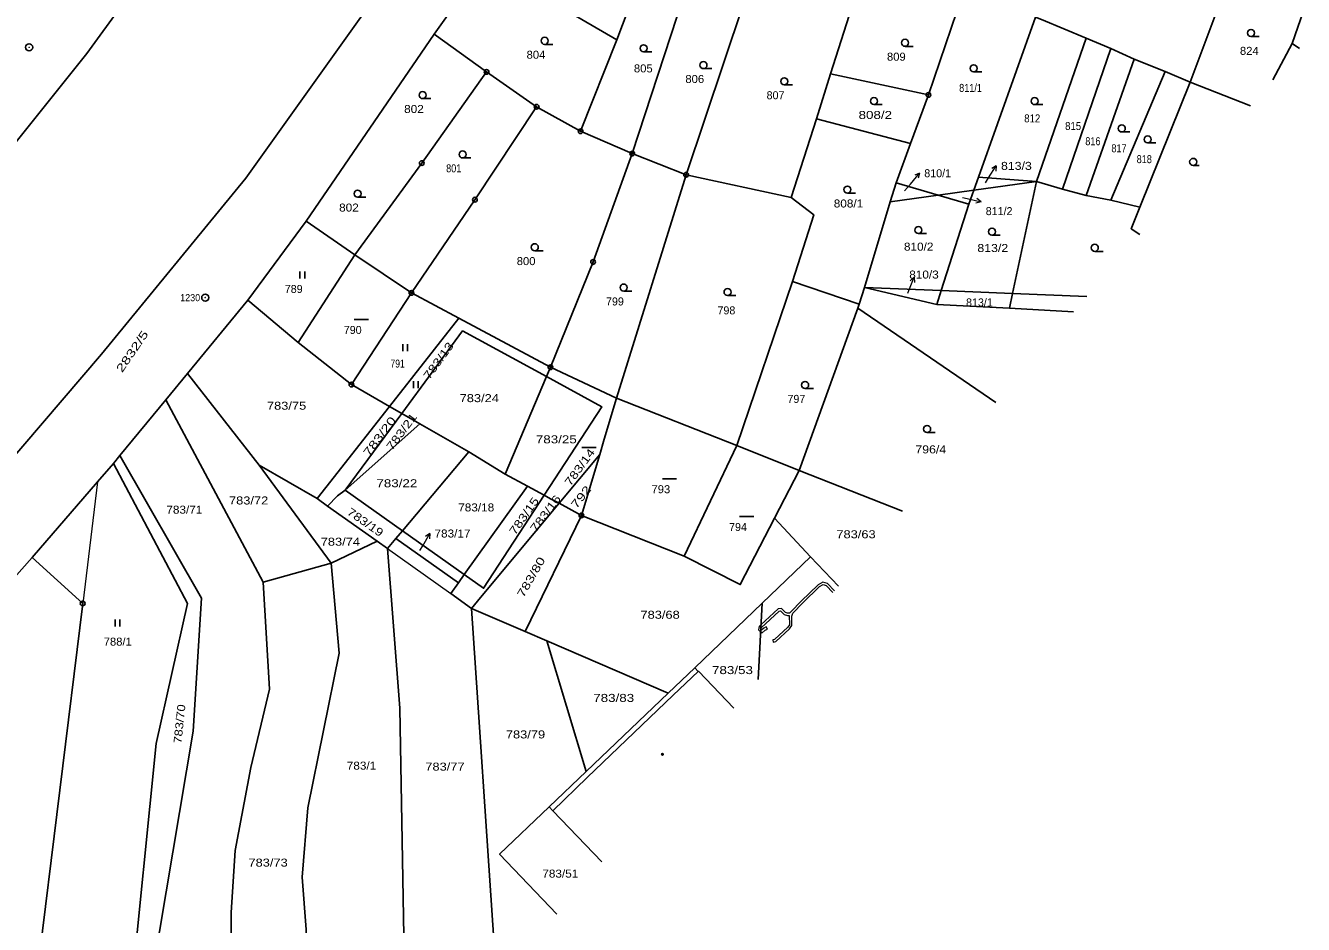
# Model space of a CAD drawing. Extents: x -546984 to -546090, y -1194931 to -1194069.
# Drawn here: x -546588.4 to -546317, y -1194754.2 to -1194563.2 of the extents above; entities that cross this region are included whole.
import ezdxf
from ezdxf.enums import TextEntityAlignment as Align

# ---------------------------------------------------------------- set-up
doc = ezdxf.new("R2010")
doc.units = 0
doc.header["$LTSCALE"] = 0.68
for name, color, linetype, lineweight in [('1', 7, 'Continuous', 25), ('13', 7, 'Continuous', 13), ('3', 7, 'Continuous', 25), ('4', 7, 'Continuous', 13), ('5', 7, 'Continuous', 25), ('7', 7, 'Continuous', 13), ('8', 7, 'Continuous', 25)]:
    doc.layers.add(name, color=color, linetype=linetype, lineweight=lineweight)
doc.layers.add('2', color=7, linetype='Continuous')

msp = doc.modelspace()

# ---------------------------------------------------------------- linework, layer by layer
at = {"layer": '1'}
for p, q in [((-546459.53, -1194590.43), (-546444.71, -1194545.11)), ((-546332.93, -1194553.62), (-546341, -1194575.24)), ((-546316.96, -1194560.09), (-546319.33, -1194567.05)), ((-546501.59, -1194565.05), (-546528.77, -1194604.78)), ((-546490.48, -1194573.07), (-546501.59, -1194565.05)), ((-546470.5, -1194585.68), (-546462.81, -1194566.22)), ((-546357.87, -1194568.11), (-546363.1, -1194565.9)), ((-546352.89, -1194570.35), (-546357.87, -1194568.11)), ((-546319.33, -1194567.05), (-546323.492, -1194574.76)), ((-546317.768, -1194568.087), (-546319.33, -1194567.05)), ((-546346.32, -1194572.96), (-546352.89, -1194570.35)), ((-546479.84, -1194580.46), (-546490.48, -1194573.07)), ((-546396.63, -1194577.94), (-546417.4, -1194573.5)), ((-546357.85, -1194600.33), (-546346.32, -1194572.96)), ((-546341, -1194575.24), (-546346.32, -1194572.96)), ((-546328.24, -1194580.295), (-546341, -1194575.24)), ((-546400.43, -1194588.27), (-546420.43, -1194583.03)), ((-546394.53, -1194599.25), (-546403.5, -1194596.62)), ((-546386.98, -1194598.21), (-546386.01, -1194595.44)), ((-546373.64, -1194596.38), (-546386.98, -1194598.21)), ((-546378.75, -1194620.15), (-546373.64, -1194596.38)), ((-546404.72, -1194600.65), (-546394.53, -1194599.25)), ((-546394.53, -1194599.25), (-546386.98, -1194598.21)), ((-546388.02, -1194601.16), (-546394.53, -1194599.25)), ((-546388.02, -1194601.16), (-546386.98, -1194598.21)), ((-546363.12, -1194599.31), (-546357.85, -1194600.33)), ((-546528.77, -1194604.78), (-546541.17, -1194621.53)), ((-546518.46, -1194611.94), (-546528.77, -1194604.78)), ((-546496.38, -1194625.39), (-546506.45, -1194620.01)), ((-546394.86, -1194622.45), (-546410.22, -1194618.84)), ((-546394.86, -1194622.45), (-546393.92, -1194619.52)), ((-546378.75, -1194620.15), (-546393.92, -1194619.52)), ((-546379.42, -1194623.27), (-546378.75, -1194620.15)), ((-546362.992, -1194620.804), (-546378.75, -1194620.15)), ((-546541.17, -1194621.53), (-546554, -1194637.12)), ((-546411.65, -1194623.24), (-546382.303, -1194643.315)), ((-546530.52, -1194630.57), (-546519.2, -1194639.51)), ((-546554, -1194637.12), (-546558.63, -1194642.75)), ((-546538.81, -1194656.63), (-546554, -1194637.12)), ((-546519.2, -1194639.51), (-546511.09, -1194644.15)), ((-546486.54, -1194658.5), (-546477.76, -1194637.81)), ((-546558.63, -1194642.75), (-546568.37, -1194654.58)), ((-546537.9, -1194681.47), (-546558.63, -1194642.75)), ((-546520.48, -1194661.94), (-546508.48, -1194645.64)), ((-546494.24, -1194653.78), (-546504.67, -1194647.82)), ((-546494.24, -1194653.78), (-546508.35, -1194670.55)), ((-546568.37, -1194654.58), (-546569.74, -1194656.25)), ((-546475.09, -1194664.7), (-546466.45, -1194654.33)), ((-546526.45, -1194663.73), (-546538.81, -1194656.63)), ((-546402.113, -1194666.407), (-546424.11, -1194657.73)), ((-546508.35, -1194670.55), (-546520.48, -1194661.94)), ((-546429.33, -1194667.88), (-546421.68, -1194676.11)), ((-546513.72, -1194672.79), (-546523.48, -1194677.44)), ((-546495.21, -1194679.88), (-546496.47, -1194681.64)), ((-546488.9, -1194757.45), (-546493.69, -1194687.04)), ((-546482.25, -1194691.97), (-546493.69, -1194687.04)), ((-546469.33, -1194721.69), (-546477.68, -1194693.94)), ((-546451.9, -1194705.05), (-546446.26, -1194699.66)), ((-546451.9, -1194705.05), (-546469.33, -1194721.69)), ((-546477.21, -1194729.22), (-546469.33, -1194721.69))]:
    msp.add_line(p, q, dxfattribs=at)
for points in [[(-546389.24, -1194211.62), (-546383.21, -1194213.85), (-546381.43, -1194214.52), (-546374.55, -1194220.96), (-546389.16, -1194255.29), (-546392.45, -1194260.52), (-546401.16, -1194281.84), (-546427.1, -1194334), (-546466.91, -1194406.62), (-546525.73, -1194500.91), (-546575.37, -1194569.17), (-546611.42, -1194614.13), (-546654.08, -1194661.28), (-546675.45, -1194680.69), (-546700.89, -1194697.8)], [(-546653.83, -1194720.11), (-546626.66, -1194696.55), (-546572.27, -1194633.02), (-546541.58, -1194595.62), (-546489.43, -1194522.46), (-546452.3, -1194465.52), (-546414.56, -1194402.38), (-546384.23, -1194347.08), (-546351.57, -1194280.62), (-546352.84, -1194277.72), (-546335.99, -1194236.72), (-546326.04, -1194236.79), (-546324.23, -1194237.51), (-546321.88, -1194231.5)], [(-546477.14, -1194530.24), (-546490.84, -1194549.86), (-546501.59, -1194565.05)], [(-546490.84, -1194549.86), (-546462.81, -1194566.22), (-546453.83, -1194542.36)], [(-546448.08, -1194594.92), (-546431.99, -1194546.91), (-546436.97, -1194546.04), (-546439.75, -1194545.56)], [(-546425.75, -1194599.76), (-546420.43, -1194583.03), (-546417.4, -1194573.5), (-546410.61, -1194552.12)], [(-546400.43, -1194588.27), (-546396.63, -1194577.94), (-546389.4, -1194556.64), (-546402.77, -1194553.75), (-546410.61, -1194552.12)], [(-546373.64, -1194596.38), (-546368.13, -1194597.96), (-546357.87, -1194568.11)], [(-546368.13, -1194597.96), (-546363.12, -1194599.31), (-546352.89, -1194570.35)], [(-546490.48, -1194573.07), (-546504.24, -1194592.44), (-546518.46, -1194611.94)], [(-546357.85, -1194600.33), (-546351.68, -1194601.82), (-546341, -1194575.24)], [(-546479.84, -1194580.46), (-546492.96, -1194600.21), (-546506.45, -1194620.01)], [(-546448.08, -1194594.92), (-546459.53, -1194590.43), (-546470.5, -1194585.68), (-546479.84, -1194580.46)], [(-546411.35, -1194622.41), (-546410.22, -1194618.84), (-546404.72, -1194600.65), (-546403.5, -1194596.62), (-546400.43, -1194588.27)], [(-546459.53, -1194590.43), (-546467.86, -1194613.45), (-546476.91, -1194635.8)], [(-546425.49, -1194617.63), (-546420.97, -1194603.4), (-546425.75, -1194599.76), (-546448.08, -1194594.92), (-546462.88, -1194642.39)], [(-546410.22, -1194618.84), (-546393.92, -1194619.52), (-546388.02, -1194601.16)], [(-546351.68, -1194601.82), (-546353.53, -1194606.4), (-546351.697, -1194607.638)], [(-546541.17, -1194621.53), (-546530.52, -1194630.57), (-546518.46, -1194611.94)], [(-546519.2, -1194639.51), (-546506.45, -1194620.01), (-546518.46, -1194611.94)], [(-546411.35, -1194622.41), (-546425.49, -1194617.63), (-546437.29, -1194652.45)], [(-546424.11, -1194657.73), (-546411.65, -1194623.24), (-546411.35, -1194622.41)], [(-546365.796, -1194624.073), (-546379.42, -1194623.27), (-546394.86, -1194622.45)], [(-546476.91, -1194635.8), (-546496.38, -1194625.39), (-546511.09, -1194644.15), (-546508.48, -1194645.64)], [(-546508.48, -1194645.64), (-546495.56, -1194628.1), (-546477.76, -1194637.81), (-546476.91, -1194635.8)], [(-546466.45, -1194654.33), (-546465.48, -1194651.07), (-546462.88, -1194642.39), (-546476.91, -1194635.8)], [(-546477.76, -1194637.81), (-546465.97, -1194644.25), (-546478.22, -1194663.01)], [(-546470.33, -1194667.29), (-546448.51, -1194675.98), (-546437.29, -1194652.45), (-546462.88, -1194642.39)], [(-546511.09, -1194644.15), (-546524.59, -1194661.37), (-546526.45, -1194663.73), (-546524.25, -1194665.3)], [(-546520.48, -1194661.94), (-546504.67, -1194647.82), (-546508.48, -1194645.64)], [(-546481.77, -1194661.08), (-546486.54, -1194658.5), (-546494.24, -1194653.78)], [(-546429.33, -1194667.88), (-546424.11, -1194657.73), (-546437.29, -1194652.45)], [(-546569.74, -1194656.25), (-546573.1, -1194660.14), (-546587.01, -1194676.23)], [(-546566.53, -1194771.87), (-546566.11, -1194770.01), (-546560.65, -1194715.77), (-546554.01, -1194686.01), (-546569.74, -1194656.25)], [(-546566.53, -1194771.87), (-546562.89, -1194773), (-546552.83, -1194713.17), (-546551.06, -1194684.9), (-546568.37, -1194654.58)], [(-546475.09, -1194664.7), (-546470.33, -1194667.29), (-546466.45, -1194654.33)], [(-546537.9, -1194681.47), (-546523.48, -1194677.44), (-546538.81, -1194656.63)], [(-546520.48, -1194661.94), (-546522.15, -1194663.11), (-546524.25, -1194665.3)], [(-546478.22, -1194663.01), (-546481.77, -1194661.08), (-546495.21, -1194679.88)], [(-546495.21, -1194679.88), (-546491.13, -1194682.78), (-546478.22, -1194663.01)], [(-546493.69, -1194687.04), (-546491.78, -1194684.74), (-546475.09, -1194664.7)], [(-546478.22, -1194663.01), (-546476.88, -1194663.74), (-546475.09, -1194664.7)], [(-546524.25, -1194665.3), (-546513.72, -1194672.79), (-546511.54, -1194674.34), (-546509.74, -1194672.2)], [(-546470.33, -1194667.29), (-546482.25, -1194691.97), (-546477.68, -1194693.94), (-546451.9, -1194705.05)], [(-546448.51, -1194675.98), (-546436.58, -1194681.99), (-546429.33, -1194667.88)], [(-546495.21, -1194679.88), (-546508.35, -1194670.55), (-546509.74, -1194672.2), (-546496.47, -1194681.64)], [(-546508.91, -1194776.49), (-546508.05, -1194756.59), (-546508.87, -1194708.28), (-546511.54, -1194674.34)], [(-546587.01, -1194676.23), (-546604.46, -1194695.9), (-546615.35, -1194707.32)], [(-546585.99, -1194765.36), (-546576.27, -1194686.01), (-546587.01, -1194676.23)], [(-546523.48, -1194677.44), (-546521.76, -1194696.57), (-546528.48, -1194729.44), (-546529.66, -1194744.16), (-546528.8, -1194755.3), (-546528.37, -1194777.02), (-546530.23, -1194801.33)], [(-546415.748, -1194682.301), (-546421.68, -1194676.11), (-546431.96, -1194685.96)], [(-546544.63, -1194778.53), (-546544.76, -1194751.68), (-546543.9, -1194738.48), (-546540.57, -1194720.86), (-546536.58, -1194704.19), (-546537.9, -1194681.47)], [(-546496.47, -1194681.64), (-546498.09, -1194683.91), (-546493.69, -1194687.04)], [(-546432.793, -1194702.171), (-546431.96, -1194685.96), (-546446.26, -1194699.66)], [(-546446.26, -1194699.66), (-546445.54, -1194700.47), (-546445.47, -1194700.4), (-546437.985, -1194708.223)], [(-546477.21, -1194729.22), (-546487.72, -1194739.3), (-546475.562, -1194752.025)], [(-546466.019, -1194740.901), (-546476.42, -1194730.04), (-546477.21, -1194729.22)]]:
    msp.add_lwpolyline(points, dxfattribs=at)
msp.add_lwpolyline([(-546373.64, -1194596.38), (-546363.1, -1194565.9), (-546372.63, -1194561.95), (-546373.86, -1194561.44), (-546386.01, -1194595.44)], close=True, dxfattribs=at)
at = {"layer": '13'}
msp.add_lwpolyline([(-546416.604, -1194683.3), (-546418.07, -1194681.76), (-546419.07, -1194681.46), (-546420.05, -1194682.02), (-546423.66, -1194685.5), (-546425.78, -1194687.73), (-546426.13, -1194688.05), (-546426.53, -1194688.08), (-546426.99, -1194687.93), (-546427.82, -1194687.09), (-546428.52, -1194687.11), (-546432.2, -1194690.53), (-546432.59, -1194690.91), (-546432.7, -1194691.58), (-546432.27, -1194692.03), (-546431.95, -1194692.23), (-546431.29, -1194691.7), (-546430.83, -1194691.44), (-546431.07, -1194691), (-546431.57, -1194691.28), (-546431.99, -1194691.61), (-546432.2, -1194691.66), (-546432.13, -1194691.15), (-546428.32, -1194687.61), (-546428.02, -1194687.59), (-546427.25, -1194688.37), (-546426.59, -1194688.58), (-546426.17, -1194688.55), (-546426.16, -1194690.51), (-546426.51, -1194691.07), (-546429.3, -1194693.65), (-546429.68, -1194693.72), (-546429.58, -1194694.22), (-546429.06, -1194694.11), (-546426.13, -1194691.39), (-546425.66, -1194690.65), (-546425.67, -1194688.71), (-546425.4, -1194688.05), (-546423.3, -1194685.86), (-546419.75, -1194682.42), (-546419.01, -1194682), (-546418.35, -1194682.2), (-546416.935, -1194683.685)], dxfattribs=at)
at = {"layer": '3'}
for p, q in [((-546328.103, -1194565.54), (-546326.353, -1194565.54)), ((-546478.143, -1194567.21), (-546476.393, -1194567.21)), ((-546457.123, -1194568.8), (-546455.373, -1194568.8)), ((-546401.593, -1194567.63), (-546399.843, -1194567.63)), ((-546444.413, -1194572.37), (-546442.663, -1194572.37)), ((-546387.003, -1194573.06), (-546385.253, -1194573.06)), ((-546427.243, -1194575.82), (-546425.493, -1194575.82)), ((-546504.065, -1194578.744), (-546502.315, -1194578.744)), ((-546408.183, -1194580.01), (-546406.433, -1194580.01)), ((-546374.063, -1194580.02), (-546372.313, -1194580.02)), ((-546355.553, -1194585.83), (-546353.803, -1194585.83)), ((-546350.053, -1194588.15), (-546348.303, -1194588.15)), ((-546495.568, -1194591.354), (-546493.818, -1194591.354)), ((-546340.383, -1194592.93), (-546339.079, -1194592.93)), ((-546413.833, -1194598.82), (-546412.083, -1194598.82)), ((-546517.874, -1194599.686), (-546516.124, -1194599.686)), ((-546398.753, -1194607.42), (-546397.003, -1194607.42)), ((-546383.113, -1194607.76), (-546381.363, -1194607.76)), ((-546480.233, -1194611.06), (-546478.483, -1194611.06)), ((-546361.283, -1194611.19), (-546359.533, -1194611.19)), ((-546530.111, -1194616.98), (-546530.111, -1194615.48)), ((-546529.11, -1194616.98), (-546529.11, -1194615.48)), ((-546461.353, -1194619.63), (-546459.603, -1194619.63)), ((-546439.283, -1194620.59), (-546437.533, -1194620.59)), ((-546518.568, -1194625.69), (-546515.568, -1194625.69)), ((-546508.291, -1194632.38), (-546508.291, -1194630.88)), ((-546507.29, -1194632.38), (-546507.29, -1194630.88)), ((-546506.021, -1194640.28), (-546506.021, -1194638.78)), ((-546505.02, -1194640.28), (-546505.02, -1194638.78)), ((-546422.813, -1194640.34), (-546421.063, -1194640.34)), ((-546396.903, -1194649.69), (-546395.153, -1194649.69)), ((-546470.208, -1194652.88), (-546467.208, -1194652.88)), ((-546453.108, -1194659.53), (-546450.108, -1194659.53)), ((-546436.718, -1194667.56), (-546433.718, -1194667.56)), ((-546569.397, -1194690.912), (-546569.397, -1194689.412)), ((-546568.396, -1194690.912), (-546568.396, -1194689.412))]:
    msp.add_line(p, q, dxfattribs=at)
for centre in [(-546328.1029, -1194564.7898), (-546478.1429, -1194566.4598), (-546401.5929, -1194566.8798), (-546457.1229, -1194568.0498), (-546444.4129, -1194571.6198), (-546387.0029, -1194572.3098), (-546427.2429, -1194575.0698), (-546504.0652, -1194577.9951), (-546408.1829, -1194579.2598), (-546374.0629, -1194579.2698), (-546355.5529, -1194585.0798), (-546350.0529, -1194587.3998), (-546495.5682, -1194590.6038), (-546340.3829, -1194592.1798), (-546517.8741, -1194598.9366), (-546413.8329, -1194598.0698), (-546398.7529, -1194606.6698), (-546383.1129, -1194607.0098), (-546480.2329, -1194610.3098), (-546361.2829, -1194610.4398), (-546461.3529, -1194618.8798), (-546439.2829, -1194619.8398), (-546422.8129, -1194639.5898), (-546396.9029, -1194648.9398)]:
    msp.add_circle(centre, 0.75, dxfattribs=at)
at = {"layer": '4'}
for p, q in [((-546573.1, -1194660.14), (-546576.27, -1194686.01)), ((-546511.54, -1194674.34), (-546498.09, -1194683.91))]:
    msp.add_line(p, q, dxfattribs=at)
msp.add_lwpolyline([(-546476.42, -1194730.04), (-546469.08, -1194723.01), (-546450.82, -1194705.52), (-546445.54, -1194700.47)], dxfattribs=at)
at = {"layer": '5'}
msp.add_circle((-546453.1168, -1194718.0692), 0.175, dxfattribs=at)
at = {"layer": '7'}
for p, q in [((-546382.196, -1194593.033), (-546383.161, -1194593.6)), ((-546398.511, -1194594.581), (-546399.538, -1194595.026)), ((-546385.446, -1194600.655), (-546386.309, -1194599.942)), ((-546399.675, -1194616.698), (-546400.501, -1194617.454)), ((-546502.54, -1194671.141), (-546503.474, -1194671.758))]:
    msp.add_line(p, q, dxfattribs=at)
for points in [[(-546384.53, -1194596.63), (-546383.83, -1194595.55), (-546382.196, -1194593.033), (-546382.321, -1194594.146)], [(-546401.68, -1194598.33), (-546400.44, -1194596.88), (-546398.511, -1194594.581), (-546398.771, -1194595.67)], [(-546389.4, -1194599.74), (-546388.37, -1194599.98), (-546385.446, -1194600.655), (-546386.534, -1194600.918)], [(-546400.97, -1194620.08), (-546400.75, -1194619.5), (-546399.675, -1194616.698), (-546399.566, -1194617.813)], [(-546504.62, -1194674.73), (-546504.04, -1194673.74), (-546502.54, -1194671.141), (-546502.607, -1194672.259)]]:
    msp.add_lwpolyline(points, dxfattribs=at)
at = {"layer": '8'}
for centre, radius in [((-546587.64, -1194567.8398), 0.75), ((-546587.64, -1194567.8398), 0.03), ((-546490.48, -1194573.0699), 0.5), ((-546490.48, -1194573.0699), 0.0303), ((-546396.63, -1194577.9399), 0.5), ((-546479.84, -1194580.4599), 0.5), ((-546479.84, -1194580.4599), 0.0303), ((-546396.63, -1194577.9399), 0.0303), ((-546470.5, -1194585.6799), 0.5), ((-546470.5, -1194585.6799), 0.0303), ((-546459.53, -1194590.4299), 0.5), ((-546459.53, -1194590.4299), 0.0303), ((-546504.24, -1194592.4399), 0.5), ((-546504.24, -1194592.4399), 0.0303), ((-546448.08, -1194594.9199), 0.5), ((-546448.08, -1194594.9199), 0.0303), ((-546492.96, -1194600.2099), 0.5), ((-546492.96, -1194600.2099), 0.0303), ((-546467.86, -1194613.4499), 0.5), ((-546467.86, -1194613.4499), 0.0303), ((-546550.24, -1194621.0298), 0.75), ((-546550.24, -1194621.0298), 0.03), ((-546506.45, -1194620.0099), 0.5), ((-546506.45, -1194620.0099), 0.0303), ((-546476.91, -1194635.7999), 0.5), ((-546476.91, -1194635.7999), 0.0303), ((-546519.2, -1194639.5099), 0.5), ((-546519.2, -1194639.5099), 0.0303), ((-546470.33, -1194667.2899), 0.5), ((-546470.33, -1194667.2899), 0.0303), ((-546576.27, -1194686.0099), 0.5), ((-546576.27, -1194686.0099), 0.0303)]:
    msp.add_circle(centre, radius, dxfattribs=at)

# ---------------------------------------------------------------- texts
at = {"layer": '2'}
for s, width, p in [('804', 1.05, (-546479.9865, -1194570.26)), ('809', 1.05, (-546403.4365, -1194570.68)), ('824', 1.05, (-546328.4595, -1194569.44)), ('805', 1.05, (-546457.1895, -1194573.17)), ('806', 1.05, (-546446.2565, -1194575.42)), ('802', 1.1, (-546505.904, -1194581.794)), ('816', 0.85, (-546361.6815, -1194588.64)), ('817', 0.85, (-546356.1415, -1194590.14)), ('818', 0.85, (-546350.771, -1194592.45)), ('801', 0.85, (-546497.4495, -1194594.403)), ('802', 1.1, (-546519.713, -1194602.736)), ('800', 1.05, (-546482.08, -1194614.11)), ('796/4', 1.15, (-546396.1205, -1194654.12)), ('793', 1.05, (-546453.4535, -1194662.58)), ('783/63', 1.2, (-546412.002, -1194672.15)), ('783/68', 1.2, (-546453.619, -1194689.25))]:
    msp.add_text(s, height=1.7, dxfattribs=dict(at, width=width)).set_placement(p, align=Align.CENTER)
for s, p in [('807', (-546429.097, -1194578.87)), ('789', (-546531.4435, -1194620.03)), ('799', (-546463.2105, -1194622.68)), ('790', (-546518.9135, -1194628.74)), ('797', (-546424.6705, -1194643.39)), ('794', (-546437.0705, -1194670.61))]:
    msp.add_text(s, height=1.7, dxfattribs=at).set_placement(p, align=Align.CENTER)
for s, width, p in [('811/1', 0.85, (-546390.09, -1194577.31)), ('808/2', 1.25, (-546411.46, -1194583.06)), ('812', 0.9, (-546376.27, -1194583.79)), ('815', 0.9, (-546367.59, -1194585.41)), ('813/3', 1.15, (-546381.2, -1194593.88)), ('808/1', 1.1, (-546416.73, -1194601.87)), ('810/2', 1.1, (-546401.82, -1194611.04)), ('813/2', 1.15, (-546386.22, -1194611.33)), ('810/3', 1.1, (-546400.69, -1194616.97)), ('791', 0.8, (-546510.89, -1194635.88)), ('783/24', 1.2, (-546496.2, -1194643.23)), ('783/75', 1.2, (-546537.13, -1194644.84)), ('783/25', 1.25, (-546480.01, -1194651.98)), ('783/22', 1.25, (-546513.88, -1194661.31)), ('783/72', 1.2, (-546545.19, -1194664.97)), ('783/18', 1.1, (-546496.5, -1194666.45)), ('783/71', 1.1, (-546558.499, -1194666.925)), ('783/74', 1.2, (-546525.71, -1194673.73)), ('783/17', 1.1, (-546501.54, -1194671.99)), ('788/1', 1.05, (-546571.806, -1194694.961)), ('783/53', 1.25, (-546442.59, -1194701.01)), ('783/83', 1.25, (-546467.82, -1194706.92)), ('783/79', 1.2, (-546486.38, -1194714.68)), ('783/1', 1.1, (-546520.17, -1194721.31)), ('783/77', 1.2, (-546503.49, -1194721.52)), ('783/73', 1.2, (-546541.061, -1194741.911)), ('783/51', 1.1, (-546478.64, -1194744.25))]:
    msp.add_text(s, height=1.7, dxfattribs=dict(at, width=width)).set_placement(p)
for s, p in [('810/1', (-546397.5, -1194595.44)), ('811/2', (-546384.45, -1194603.493)), ('813/1', (-546388.63, -1194622.89)), ('798', (-546441.43, -1194624.58))]:
    msp.add_text(s, height=1.7, dxfattribs=at).set_placement(p)
for s, rotation, width, p in [('2832/5', 55.644, 1.45, (-546567.896, -1194637.08)), ('783/13', 54, 1.3, (-546502.662, -1194638.569)), ('783/20', 53, 1.4, (-546515.451, -1194654.891)), ('783/21', 53, 1.3, (-546510.561, -1194653.621)), ('783/14', 54, 1.3, (-546472.662, -1194661.199)), ('783/15', 55, 1.3, (-546484.413, -1194671.597)), ('783/16', 53, 1.3, (-546480.001, -1194670.991)), ('783/19', 325, 1.25, (-546520.267, -1194666.936)), ('783/80', 60, 1.35, (-546482.623, -1194684.885)), ('783/70', 84, 1.2, (-546555.297, -1194715.832))]:
    msp.add_text(s, height=1.7, rotation=rotation, dxfattribs=dict(at, width=width)).set_placement(p)
at = {"layer": '2', "width": 1.4}
msp.add_text('792', height=1.7, rotation=52, dxfattribs=at).set_placement((-546469.7434, -1194663.8993), align=Align.CENTER)
at = {"layer": '8', "width": 0.95}
msp.add_text('1230', height=1.5, dxfattribs=at).set_placement((-546551.319, -1194621.78), align=Align.RIGHT)

doc.saveas('drawing.dxf')
